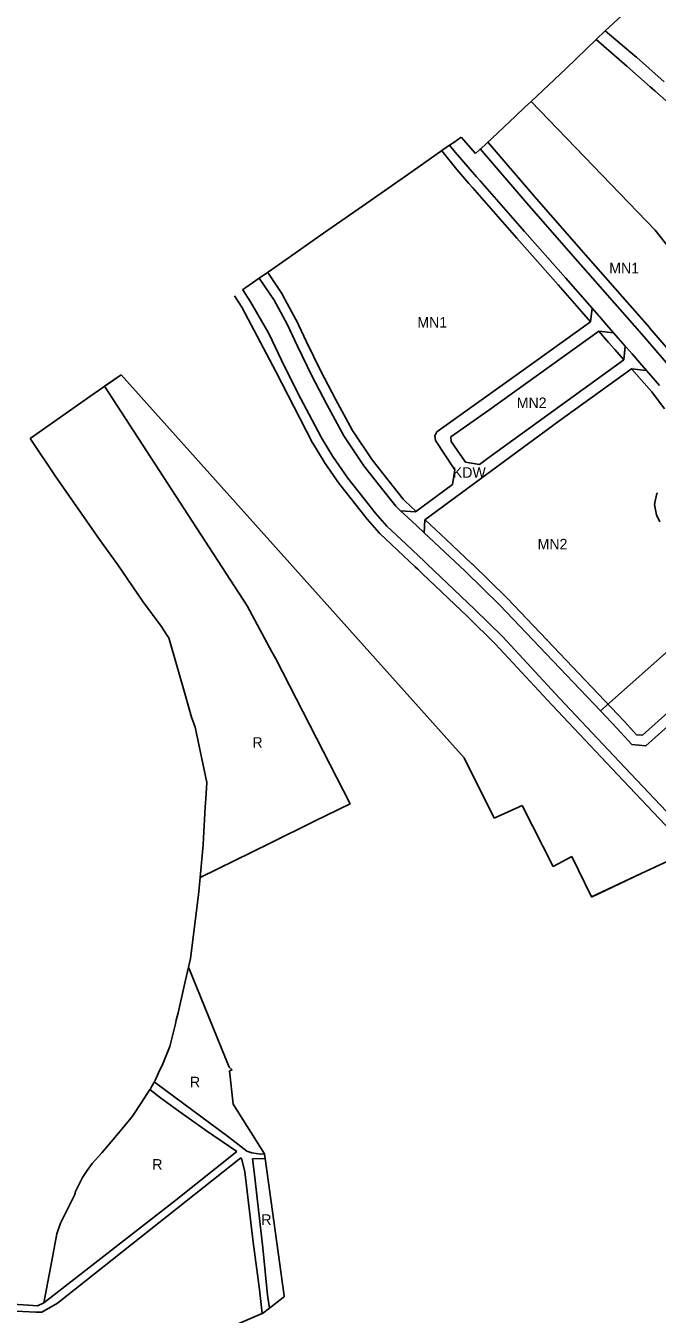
# Model space of a CAD drawing. Extents: x 7435758 to 7439981, y 5550649 to 5554049.
# Drawn here: x 7436433 to 7436745, y 5551729 to 5552365 of the extents above; entities that cross this region are included whole.
import ezdxf

# ---------------------------------------------------------------- set-up
doc = ezdxf.new("R2010")
doc.units = 0
for name, color, linetype in [('info', 7, 'Continuous'), ('linie_rozgraniczające', 7, 'Continuous'), ('linie_zabudowy_nieprzekraczalne', 7, 'Continuous'), ('oznaczenia_przeznaczen', 7, 'Continuous')]:
    doc.layers.add(name, color=color, linetype=linetype)

msp = doc.modelspace()

# ---------------------------------------------------------------- linework, layer by layer
at = {"layer": 'info'}
for p, q in [((7436480.27, 5552192.63), (7436472.16, 5552186.9)), ((7436649.48, 5552003.73), (7436480.27, 5552192.63)), ((7436472.16, 5552186.9), (7436542.43, 5552078.58)), ((7436664.16, 5551973.94), (7436649.48, 5552003.73)), ((7436678, 5551980.14), (7436664.16, 5551973.94)), ((7436693.32, 5551950.07), (7436678, 5551980.14)), ((7436702.51, 5551955.14), (7436693.32, 5551950.07)), ((7436712.13, 5551935.11), (7436702.51, 5551955.14)), ((7436750.08, 5551952.93), (7436736.66, 5551946.62)), ((7436736.66, 5551946.62), (7436712.13, 5551935.1)), ((7436712.13, 5551935.1), (7436712.13, 5551935.11)), ((7436514.57, 5551904.75), (7436513.59, 5551900.47)), ((7436513.59, 5551900.47), (7436533.63, 5551851.18)), ((7436533.63, 5551851.18), (7436534.98, 5551849.97)), ((7436534.98, 5551849.97), (7436533.81, 5551849.48)), ((7436560.23, 5551737.61), (7436553.41, 5551732.38)), ((7436560.7, 5551737.97), (7436560.23, 5551737.61)), ((7436549.92, 5551729.75), (7436534.97, 5551723.42)), ((7436550.04, 5551729.8), (7436549.92, 5551729.75)), ((7436553.41, 5551732.38), (7436550.04, 5551729.8))]:
    msp.add_line(p, q, dxfattribs=at)
for points in [[(7436542.43, 5552078.58), (7436554.64, 5552056.01), (7436556.54, 5552052.5), (7436593.17, 5551981.05), (7436575.63, 5551972.43), (7436553.46, 5551961.56), (7436519.23, 5551944.75), (7436518.44, 5551936.13), (7436514.57, 5551904.75)], [(7436533.81, 5551849.48), (7436535.56, 5551832.98), (7436549, 5551811.54), (7436550.94, 5551808.45)], [(7436550.94, 5551808.45), (7436550.99, 5551808.37), (7436551.29, 5551806.19), (7436560.62, 5551738.53), (7436560.7, 5551737.97)]]:
    msp.add_lwpolyline(points, dxfattribs=at)
at = {"layer": 'linie_rozgraniczające'}
for p, q in [((7436719, 5552362.18), (7436734.94, 5552376.74)), ((7436699.7, 5552343.51), (7436714.41, 5552357.83)), ((7436714.41, 5552357.83), (7436719, 5552362.18)), ((7436714.41, 5552357.83), (7436729.68, 5552344.79)), ((7436733.68, 5552349.73), (7436719, 5552362.18)), ((7436682.42, 5552327.36), (7436699.7, 5552343.51)), ((7436729.68, 5552344.79), (7436741.13, 5552334.61)), ((7436734.36, 5552349.15), (7436733.68, 5552349.73)), ((7436748.06, 5552337.04), (7436734.36, 5552349.15)), ((7436741.13, 5552334.61), (7436743.48, 5552332.53)), ((7436743.48, 5552332.53), (7436758.9, 5552319)), ((7436674.72, 5552320.14), (7436679.35, 5552324.5)), ((7436679.35, 5552324.5), (7436682.42, 5552327.36)), ((7436743.6, 5552263.84), (7436682.42, 5552327.36)), ((7436657.44, 5552303.88), (7436674.72, 5552320.14)), ((7436623.75, 5552292.81), (7436641.77, 5552305.41)), ((7436641.77, 5552305.41), (7436642.21, 5552305.72)), ((7436642.21, 5552305.72), (7436644.29, 5552307.18)), ((7436642.21, 5552305.72), (7436645.04, 5552302.41)), ((7436644.29, 5552307.18), (7436647.88, 5552309.69)), ((7436647.88, 5552309.69), (7436655.06, 5552301.64)), ((7436645.04, 5552302.41), (7436648.3, 5552298.6)), ((7436655.06, 5552301.64), (7436657.17, 5552303.63)), ((7436657.17, 5552303.63), (7436657.44, 5552303.88)), ((7436680.33, 5552277.2), (7436657.44, 5552303.88)), ((7436601.5, 5552277.15), (7436623.75, 5552292.81)), ((7436648.3, 5552298.6), (7436655.54, 5552290.15)), ((7436655.54, 5552290.15), (7436657.3, 5552288.2)), ((7436657.3, 5552288.2), (7436679.16, 5552263.3)), ((7436580.15, 5552262.33), (7436601.5, 5552277.15)), ((7436703.17, 5552251.13), (7436680.33, 5552277.2)), ((7436561.67, 5552249.43), (7436580.15, 5552262.33)), ((7436679.16, 5552263.3), (7436699.47, 5552240.22)), ((7436805.24, 5552185.29), (7436743.6, 5552263.84)), ((7436552.97, 5552243.35), (7436561.67, 5552249.43)), ((7436733.34, 5552216.78), (7436703.17, 5552251.13)), ((7436548.42, 5552240.17), (7436552.97, 5552243.35)), ((7436540.22, 5552234.44), (7436548.42, 5552240.17)), ((7436555.68, 5552229.34), (7436548.42, 5552240.17)), ((7436699.47, 5552240.22), (7436712.48, 5552225.41)), ((7436540.22, 5552234.44), (7436540.27, 5552234.38)), ((7436540.27, 5552234.38), (7436544.14, 5552228.6)), ((7436562.1, 5552217.46), (7436555.68, 5552229.34)), ((7436544.14, 5552228.6), (7436553.18, 5552212.92)), ((7436712.48, 5552225.41), (7436711.75, 5552218.76)), ((7436712.48, 5552225.41), (7436715.76, 5552221.66)), ((7436567.22, 5552206.72), (7436562.1, 5552217.46)), ((7436711.75, 5552218.76), (7436677.43, 5552193.95)), ((7436715.76, 5552221.66), (7436716.11, 5552221.27)), ((7436716.11, 5552221.27), (7436719.82, 5552217.01)), ((7436719.82, 5552217.01), (7436723.1, 5552213.23)), ((7436737.06, 5552212.54), (7436733.34, 5552216.78)), ((7436553.18, 5552212.92), (7436561.08, 5552196.38)), ((7436715.79, 5552214.12), (7436661.52, 5552175.12)), ((7436723.1, 5552213.23), (7436715.79, 5552214.12)), ((7436723.1, 5552213.23), (7436725.32, 5552210.68)), ((7436725.32, 5552210.68), (7436728.82, 5552206.65)), ((7436753.92, 5552192.88), (7436737.06, 5552212.54)), ((7436574.3, 5552192.11), (7436567.22, 5552206.72)), ((7436728.08, 5552199.9), (7436728.82, 5552206.65)), ((7436728.82, 5552206.65), (7436729.22, 5552206.19)), ((7436729.22, 5552206.19), (7436732.16, 5552202.85)), ((7436660.97, 5552151.35), (7436728.08, 5552199.9)), ((7436732.16, 5552202.85), (7436736, 5552198.47)), ((7436736, 5552198.47), (7436739.31, 5552194.7)), ((7436465.42, 5552182.15), (7436480.27, 5552192.63)), ((7436480.27, 5552192.63), (7436649.48, 5552003.73)), ((7436561.08, 5552196.38), (7436568.83, 5552180.75)), ((7436581.53, 5552178.18), (7436574.3, 5552192.11)), ((7436677.43, 5552193.95), (7436635.93, 5552164.48)), ((7436731.96, 5552195.55), (7436696.1, 5552169.7)), ((7436739.31, 5552194.7), (7436731.96, 5552195.55)), ((7436739.31, 5552194.7), (7436745.79, 5552187.3)), ((7436435.45, 5552161.16), (7436465.42, 5552182.15)), ((7436568.83, 5552180.75), (7436572.96, 5552172.99)), ((7436572.96, 5552172.99), (7436578.95, 5552161.74)), ((7436590.1, 5552162.54), (7436581.53, 5552178.18)), ((7436661.52, 5552175.12), (7436642.85, 5552161.98)), ((7436696.1, 5552169.7), (7436630.03, 5552121.05)), ((7436447.75, 5552142.71), (7436435.45, 5552161.16)), ((7436578.95, 5552161.74), (7436579.1, 5552161.45)), ((7436579.1, 5552161.45), (7436584.65, 5552152.25)), ((7436600.01, 5552147.75), (7436590.1, 5552162.54)), ((7436635.93, 5552164.48), (7436635, 5552162.42)), ((7436635, 5552162.42), (7436635.35, 5552160.16)), ((7436635.35, 5552160.16), (7436644.23, 5552146.63)), ((7436642.85, 5552161.98), (7436642.95, 5552159.71)), ((7436642.95, 5552159.71), (7436650.07, 5552149.53)), ((7436584.65, 5552152.25), (7436592.13, 5552141.59)), ((7436607.98, 5552137.55), (7436600.01, 5552147.75)), ((7436644.23, 5552146.63), (7436644.88, 5552145.67)), ((7436650.07, 5552149.53), (7436657, 5552148.41)), ((7436657, 5552148.41), (7436660.97, 5552151.35)), ((7436469.63, 5552111.39), (7436447.75, 5552142.71)), ((7436592.13, 5552141.59), (7436600.1, 5552131.39)), ((7436644.88, 5552145.67), (7436643.71, 5552138.56)), ((7436615.72, 5552127.77), (7436607.98, 5552137.55)), ((7436643.71, 5552138.56), (7436625.44, 5552125.01)), ((7436600.1, 5552131.39), (7436605.57, 5552124.47)), ((7436616.77, 5552126.8), (7436615.72, 5552127.77)), ((7436605.57, 5552124.47), (7436611.23, 5552117.98)), ((7436618.09, 5552125.56), (7436616.77, 5552126.8)), ((7436621.66, 5552122.21), (7436618.09, 5552125.56)), ((7436625.44, 5552125.01), (7436618.09, 5552125.56)), ((7436626.04, 5552118.11), (7436621.66, 5552122.21)), ((7436611.23, 5552117.98), (7436620.8, 5552109.02)), ((7436629.69, 5552114.68), (7436626.04, 5552118.11)), ((7436630.03, 5552121.05), (7436629.69, 5552114.68)), ((7436478.72, 5552098.8), (7436469.63, 5552111.39)), ((7436620.8, 5552109.02), (7436629.85, 5552100.56)), ((7436639.76, 5552105.23), (7436629.69, 5552114.68)), ((7436649.86, 5552095.77), (7436639.76, 5552105.23)), ((7436490.95, 5552080.87), (7436478.72, 5552098.8)), ((7436629.85, 5552100.56), (7436631.24, 5552099.23)), ((7436631.24, 5552099.23), (7436654.58, 5552076.97)), ((7436666.93, 5552078.97), (7436649.86, 5552095.77)), ((7436500.13, 5552068.6), (7436490.95, 5552080.87)), ((7436654.58, 5552076.97), (7436668.52, 5552063.33)), ((7436686.62, 5552058.46), (7436666.93, 5552078.97)), ((7436503.04, 5552064.1), (7436500.13, 5552068.6)), ((7436503.85, 5552062.85), (7436503.04, 5552064.1)), ((7436716.64, 5552026.84), (7436761.03, 5552066.45)), ((7436511.98, 5552034.29), (7436503.85, 5552062.85)), ((7436668.52, 5552063.33), (7436696.39, 5552033.17)), ((7436716.64, 5552026.84), (7436686.62, 5552058.46)), ((7436514.97, 5552023.8), (7436511.98, 5552034.29)), ((7436696.39, 5552033.17), (7436728.65, 5551998.96)), ((7436768.64, 5552036.13), (7436739.01, 5552009.68)), ((7436724.72, 5552018.34), (7436716.64, 5552026.84)), ((7436516.77, 5552018.9), (7436514.97, 5552023.8)), ((7436522.51, 5551991.53), (7436516.77, 5552018.9)), ((7436732.02, 5552010.27), (7436724.72, 5552018.34)), ((7436739.01, 5552009.68), (7436732.02, 5552010.27)), ((7436649.48, 5552003.73), (7436664.16, 5551973.94)), ((7436728.65, 5551998.96), (7436755.06, 5551970.94)), ((7436522.03, 5551983.45), (7436522.51, 5551991.53)), ((7436521.81, 5551979.6), (7436522.03, 5551983.45)), ((7436520.72, 5551961.01), (7436521.81, 5551979.6)), ((7436664.16, 5551973.94), (7436678, 5551980.14)), ((7436678, 5551980.14), (7436693.32, 5551950.07)), ((7436519.39, 5551946.49), (7436520.7, 5551960.79)), ((7436520.7, 5551960.79), (7436520.72, 5551961.01)), ((7436693.32, 5551950.07), (7436702.51, 5551955.14)), ((7436702.51, 5551955.14), (7436712.13, 5551935.11)), ((7436750.08, 5551952.93), (7436736.66, 5551946.62)), ((7436518.44, 5551936.13), (7436519.23, 5551944.76)), ((7436519.23, 5551944.76), (7436519.39, 5551946.49)), ((7436736.66, 5551946.62), (7436712.13, 5551935.11)), ((7436514.57, 5551904.75), (7436518.44, 5551936.13)), ((7436511.63, 5551891.93), (7436513.59, 5551900.47)), ((7436513.59, 5551900.47), (7436514.57, 5551904.75)), ((7436508.36, 5551877.97), (7436511.63, 5551891.93)), ((7436507.17, 5551872.5), (7436507.51, 5551874.34)), ((7436507.51, 5551874.34), (7436508.36, 5551877.97)), ((7436504.29, 5551861.32), (7436507.17, 5551872.5)), ((7436500.88, 5551852.89), (7436504.29, 5551861.32)), ((7436497.05, 5551844.64), (7436498.81, 5551848.42)), ((7436498.81, 5551848.42), (7436500.88, 5551852.89)), ((7436495.3, 5551841.47), (7436495.75, 5551842.26)), ((7436495.75, 5551842.26), (7436496.42, 5551843.41)), ((7436496.42, 5551843.41), (7436496.71, 5551843.91)), ((7436496.71, 5551843.91), (7436496.73, 5551843.95)), ((7436497.33, 5551843.48), (7436496.71, 5551843.91)), ((7436496.73, 5551843.95), (7436497.05, 5551844.64)), ((7436533.45, 5551816.62), (7436497.33, 5551843.48)), ((7436490.32, 5551833.79), (7436494.49, 5551840.13)), ((7436494.49, 5551840.13), (7436494.78, 5551840.57)), ((7436494.49, 5551840.13), (7436499.66, 5551836.16)), ((7436494.78, 5551840.57), (7436495.3, 5551841.47)), ((7436499.66, 5551836.16), (7436508.73, 5551829.48)), ((7436485.87, 5551827.01), (7436490.32, 5551833.79)), ((7436508.73, 5551829.48), (7436522.41, 5551819.79)), ((7436480.63, 5551820.7), (7436485.87, 5551827.01)), ((7436475.39, 5551814.39), (7436480.63, 5551820.7)), ((7436522.41, 5551819.79), (7436537.39, 5551809.63)), ((7436542.25, 5551809.85), (7436533.45, 5551816.62)), ((7436470.74, 5551809.01), (7436475.39, 5551814.39)), ((7436544.72, 5551809.05), (7436542.25, 5551809.85)), ((7436448.94, 5551734.84), (7436539.29, 5551806.52)), ((7436463.66, 5551800.25), (7436466.09, 5551803.64)), ((7436466.09, 5551803.64), (7436470.74, 5551809.01)), ((7436537.39, 5551809.63), (7436506.61, 5551785.16)), ((7436539.29, 5551806.52), (7436539.81, 5551805.67)), ((7436539.81, 5551805.67), (7436541.35, 5551799.53)), ((7436549.1, 5551808.33), (7436544.72, 5551809.05)), ((7436545.01, 5551806.04), (7436551.29, 5551806.18)), ((7436545.98, 5551799.66), (7436545.01, 5551806.04)), ((7436550.98, 5551808.46), (7436549.1, 5551808.33)), ((7436461.22, 5551796.87), (7436463.66, 5551800.25)), ((7436541.35, 5551799.53), (7436545.49, 5551764.99)), ((7436550.12, 5551762.15), (7436545.98, 5551799.66)), ((7436457.9, 5551789.98), (7436461.22, 5551796.87)), ((7436506.61, 5551785.16), (7436442.28, 5551734.98)), ((7436450.42, 5551774.23), (7436457.28, 5551788.04)), ((7436457.28, 5551788.04), (7436457.59, 5551789.01)), ((7436457.59, 5551789.01), (7436457.9, 5551789.98)), ((7436448.63, 5551768.97), (7436450.42, 5551774.23)), ((7436445.44, 5551752.31), (7436448.63, 5551768.97)), ((7436545.49, 5551764.99), (7436548.46, 5551741.52)), ((7436552.42, 5551738.86), (7436550.12, 5551762.15)), ((7436442.28, 5551734.98), (7436445.44, 5551752.31)), ((7436236.93, 5551740.74), (7436438.25, 5551730.35)), ((7436548.46, 5551741.52), (7436549.92, 5551729.75)), ((7436375.57, 5551737.48), (7436434.62, 5551733.86)), ((7436434.62, 5551733.86), (7436439.02, 5551733.54)), ((7436439.02, 5551733.54), (7436442.28, 5551734.98)), ((7436441.23, 5551730.48), (7436448.94, 5551734.84)), ((7436553.41, 5551732.38), (7436552.42, 5551738.86)), ((7436438.25, 5551730.35), (7436441.23, 5551730.48))]:
    msp.add_line(p, q, dxfattribs=at)
at = {"layer": 'linie_zabudowy_nieprzekraczalne'}
msp.add_line((7436564.34, 5552178.53), (7436564.41, 5552178.4), dxfattribs=at)
for points in [[(7436661.08, 5552307.31), (7436661.24, 5552307.14), (7436684.11, 5552280.48), (7436706.93, 5552254.42), (7436740.82, 5552215.83), (7436740.86, 5552215.79), (7436757.72, 5552196.14), (7436757.76, 5552196.08), (7436757.88, 5552195.93), (7436771.77, 5552177.9), (7436771.8, 5552177.86), (7436775.61, 5552172.65), (7436778.9, 5552172.22), (7436796.92, 5552187.16), (7436797.17, 5552187.35), (7436797.44, 5552187.54), (7436797.72, 5552187.7), (7436798.01, 5552187.85), (7436798.31, 5552187.98), (7436798.37, 5552188), (7436801.72, 5552189.24), (7436801.98, 5552189.33), (7436802.01, 5552189.34)], [(7436711.75, 5552218.76), (7436707.27, 5552223.76), (7436695.71, 5552236.92), (7436675.41, 5552260), (7436675.41, 5552260), (7436653.56, 5552284.88), (7436651.83, 5552286.8), (7436651.74, 5552286.89), (7436645.84, 5552293.79), (7436638.33, 5552303.05)], [(7436552.58, 5552242.96), (7436559.84, 5552232.12), (7436559.91, 5552232.01), (7436560.08, 5552231.73), (7436560.08, 5552231.72), (7436566.5, 5552219.83), (7436566.62, 5552219.61), (7436571.73, 5552208.89), (7436578.78, 5552194.36), (7436585.94, 5552180.53), (7436594.39, 5552165.14), (7436604.07, 5552150.69), (7436611.91, 5552140.64), (7436619.4, 5552131.18), (7436620.16, 5552130.48), (7436620.19, 5552130.45), (7436625.76, 5552125.22)], [(7436751.42, 5551967.51), (7436725.01, 5551995.53), (7436692.75, 5552029.74), (7436692.71, 5552029.78), (7436664.94, 5552059.84), (7436651.1, 5552073.38), (7436628.92, 5552094.5), (7436626.58, 5552096.75), (7436625.32, 5552097.95), (7436607.81, 5552114.32), (7436607.6, 5552114.53), (7436607.45, 5552114.69), (7436601.8, 5552121.19), (7436601.73, 5552121.27), (7436601.65, 5552121.37), (7436596.17, 5552128.29), (7436596.16, 5552128.31), (7436588.19, 5552138.51), (7436588.08, 5552138.65), (7436588.03, 5552138.72), (7436580.56, 5552149.38), (7436580.43, 5552149.58), (7436580.37, 5552149.67), (7436574.82, 5552158.87), (7436574.71, 5552159.06), (7436574.68, 5552159.1), (7436556.6, 5552194.16), (7436556.56, 5552194.23), (7436539.89, 5552225.95), (7436536.18, 5552231.49)], [(7436728.08, 5552199.9), (7436723.62, 5552205.02), (7436720.59, 5552208.5), (7436715.79, 5552214.12)], [(7436748.24, 5552175.75), (7436741.91, 5552184.15), (7436736.82, 5552189.95), (7436731.96, 5552195.55)], [(7436745.85, 5552120.09), (7436744.43, 5552123.14), (7436744.42, 5552123.15), (7436744.29, 5552123.45), (7436744.19, 5552123.76), (7436744.1, 5552124.07), (7436744.05, 5552124.29), (7436743.4, 5552127.63), (7436743.38, 5552127.73), (7436743.33, 5552128.06), (7436743.31, 5552128.38), (7436743.31, 5552128.71), (7436743.33, 5552129.04), (7436743.37, 5552129.36), (7436743.42, 5552129.65), (7436744.18, 5552133.17), (7436744.19, 5552133.21), (7436744.27, 5552133.53), (7436744.38, 5552133.84), (7436744.5, 5552134.14), (7436744.64, 5552134.44)], [(7436630.15, 5552121.11), (7436643.19, 5552108.88), (7436643.39, 5552108.68), (7436643.61, 5552108.44), (7436653.28, 5552099.41), (7436653.36, 5552099.33), (7436670.44, 5552082.54), (7436670.54, 5552082.43), (7436690.22, 5552061.92), (7436690.24, 5552061.91), (7436690.24, 5552061.9), (7436728.35, 5552021.78), (7436728.43, 5552021.69), (7436734.4, 5552015.09), (7436737.28, 5552014.85), (7436765.31, 5552039.86)]]:
    msp.add_lwpolyline(points, dxfattribs=at)

# ---------------------------------------------------------------- texts
at = {"layer": 'oznaczenia_przeznaczen'}
for s, p in [('MN1', (7436720.95, 5552242.58)), ('MN1', (7436626.35, 5552215.82)), ('MN2', (7436675.35, 5552176.17)), ('KDW', (7436643.85, 5552141.81)), ('MN2', (7436685.63, 5552106.48)), ('R', (7436545.04, 5552008.69)), ('R', (7436514.26, 5551841.29)), ('R', (7436495.67, 5551800.68)), ('R', (7436549.4, 5551773.46))]:
    msp.add_text(s, height=5.2, dxfattribs=at).set_placement(p)

doc.saveas('drawing.dxf')
